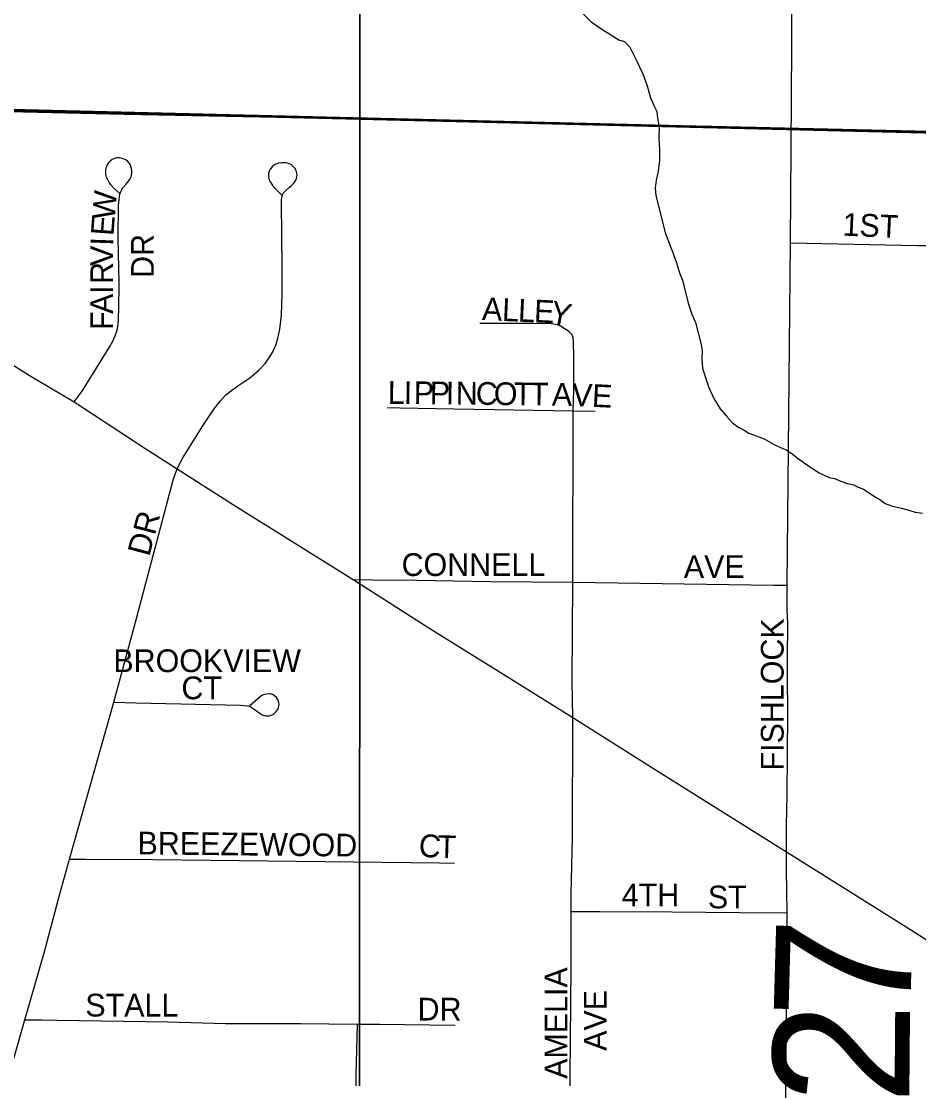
# Model space of a CAD drawing. Extents: x 0 to 68, y 0 to 52.9.
# Drawn here: x 44.8116 to 45.2063, y 37.5049 to 37.9697 of the extents above; entities that cross this region are included whole.
import ezdxf

# ---------------------------------------------------------------- set-up
doc = ezdxf.new("R2010")
doc.units = 0
for name, color, linetype in [('Default', 7, 'Continuous'), ('GM_X_Minor_River', 7, 'Continuous'), ('GM_X_State_Route', 7, 'Continuous'), ('GM_X_Township', 7, 'Continuous'), ('GM_X_Township_Road', 7, 'Continuous'), ('GM_X_Township_Road_Text', 7, 'Continuous')]:
    doc.layers.add(name, color=color, linetype=linetype)

msp = doc.modelspace()

# ---------------------------------------------------------------- linework, layer by layer
at = {"layer": 'Default'}
for points in [[(45.79985, 39.21605), (45.7821, 37.90702), (45.7586, 37.9073), (44.45233, 37.93902), (44.47349, 39.25009)], [(43.93627, 38.46518), (44.96064, 38.44451), (44.96032, 37.38586), (43.92065, 37.39833), (43.9204, 37.41034)], [(44.96064, 38.44451), (46.03674, 38.4191), (46.02513, 37.36139), (44.96032, 37.38586)], [(44.41032, 37.93957), (44.45233, 37.93902), (45.7586, 37.9073), (45.68961, 36.62483), (44.34414, 36.66665)]]:
    msp.add_lwpolyline(points, close=True, dxfattribs=at)
for points in [[(45.14983, 37.87233), (45.15013, 37.91343), (45.15051, 37.95911), (45.15046, 37.97539), (45.15077, 38.01402)], [(44.83491, 37.80242), (44.83843, 37.8072), (44.84687, 37.82055), (44.84872, 37.8237), (44.85069, 37.82675), (44.85195, 37.8291), (44.85286, 37.8311), (44.85349, 37.83299), (44.85395, 37.83471), (44.85423, 37.83671), (44.85441, 37.83808), (44.85446, 37.83992), (44.85461, 37.84297), (44.85474, 37.85476), (44.85422, 37.87439), (44.8545, 37.88879), (44.85467, 37.89131), (44.85502, 37.89368), (44.85525, 37.89449), (44.85553, 37.89509), (44.8559, 37.8957), (44.85638, 37.89646), (44.85759, 37.89789), (44.85828, 37.89874), (44.85912, 37.89986), (44.85955, 37.90051), (44.85993, 37.90131), (44.86017, 37.90211), (44.86029, 37.90307), (44.86028, 37.90413), (44.86017, 37.90493), (44.85992, 37.90586), (44.85964, 37.90653), (44.85912, 37.90734), (44.85849, 37.90802), (44.85763, 37.90877), (44.85696, 37.90915), (44.85608, 37.90945), (44.85489, 37.90968), (44.85368, 37.90963), (44.85265, 37.90938), (44.85163, 37.90893), (44.85071, 37.90824), (44.84997, 37.9075), (44.8494, 37.90664), (44.84902, 37.90561), (44.84877, 37.90447), (44.84871, 37.90382), (44.84868, 37.90306), (44.84876, 37.90231), (44.84901, 37.90125), (44.84952, 37.90014), (44.85032, 37.89875), (44.85096, 37.89789), (44.85242, 37.89631), (44.85484, 37.89419)], [(44.88016, 37.77305), (44.88269, 37.77783), (44.88633, 37.78369), (44.89116, 37.79152), (44.89606, 37.79875), (44.89907, 37.80274), (44.90168, 37.80555), (44.90418, 37.80736), (44.90695, 37.8095), (44.9121, 37.81301), (44.91611, 37.81642), (44.91898, 37.81934), (44.92102, 37.82219), (44.92247, 37.82471), (44.92357, 37.82739), (44.92445, 37.83029), (44.92537, 37.83438), (44.92604, 37.84047), (44.92636, 37.84997), (44.92635, 37.86192), (44.92604, 37.88969), (44.92612, 37.89125), (44.92625, 37.89217), (44.92645, 37.8931), (44.92667, 37.89369), (44.92702, 37.89432), (44.9274, 37.8948), (44.92816, 37.89545), (44.92966, 37.89675), (44.93053, 37.8975), (44.93153, 37.89856), (44.93234, 37.89981), (44.93272, 37.90062), (44.9329, 37.90156), (44.93294, 37.90213), (44.93287, 37.90291), (44.93271, 37.90364), (44.93246, 37.9043), (44.93204, 37.905), (44.93166, 37.90548), (44.93084, 37.90629), (44.93034, 37.90668), (44.92941, 37.9071), (44.92874, 37.9073), (44.92799, 37.90744), (44.927, 37.90751), (44.92605, 37.90746), (44.92481, 37.9073), (44.92416, 37.90709), (44.92355, 37.90685), (44.92267, 37.90635), (44.92192, 37.90568), (44.9212, 37.90481), (44.92088, 37.90426), (44.92068, 37.90373), (44.92043, 37.90273), (44.92034, 37.902), (44.92043, 37.90111), (44.92069, 37.90007), (44.92104, 37.89917), (44.92168, 37.89824), (44.92219, 37.89751), (44.92293, 37.89662), (44.92606, 37.89345)], [(45.14839, 37.72184), (45.14983, 37.87233)], [(45.14983, 37.87233), (45.20588, 37.87118), (45.22404, 37.87118), (45.23011, 37.87102)], [(45.0133, 37.83707), (45.03691, 37.83701), (45.04455, 37.83692), (45.04587, 37.83679), (45.04713, 37.83648), (45.04868, 37.83587), (45.0512, 37.83427)], [(45.05433, 37.79849), (45.05458, 37.80758), (45.05456, 37.82441), (45.05452, 37.8267), (45.05448, 37.82884), (45.05425, 37.83068), (45.05401, 37.83143), (45.0537, 37.83207), (45.05259, 37.83328), (45.0512, 37.83427)], [(44.97273, 37.79998), (44.97805, 37.7998), (45.00221, 37.79936), (45.05433, 37.79849)], [(45.05412, 37.72312), (45.05433, 37.79849)], [(45.05433, 37.79849), (45.06403, 37.79835)], [(44.85236, 37.67039), (44.86189, 37.70565), (44.87027, 37.7371), (44.87854, 37.76854), (44.88016, 37.77305)], [(44.95765, 37.72432), (44.96631, 37.72424), (44.98563, 37.72405), (45.01796, 37.72346), (45.05412, 37.72312)], [(45.05414, 37.66367), (45.05388, 37.6798), (45.05412, 37.72312)], [(45.05412, 37.72312), (45.14238, 37.72193), (45.14839, 37.72184)], [(45.14861, 37.69017), (45.14866, 37.70476), (45.14847, 37.71129), (45.14839, 37.72184)], [(45.14814, 37.60465), (45.14814, 37.61635), (45.14836, 37.62942), (45.14867, 37.66545), (45.14858, 37.68185), (45.14861, 37.69017)], [(44.83295, 37.60148), (44.85236, 37.67039)], [(44.85236, 37.67039), (44.86198, 37.67016), (44.90803, 37.66909), (44.90971, 37.66899), (44.91133, 37.66878), (44.91237, 37.66848), (44.91308, 37.66812), (44.91381, 37.66756), (44.91453, 37.66704), (44.91563, 37.66626), (44.91675, 37.66543), (44.91761, 37.66494), (44.9184, 37.66461), (44.91921, 37.66443), (44.91993, 37.6644), (44.92077, 37.66452), (44.92156, 37.6647), (44.92238, 37.66509), (44.92299, 37.66555), (44.92345, 37.66602), (44.92387, 37.6665), (44.92435, 37.6671), (44.92462, 37.66757), (44.92484, 37.66819), (44.92495, 37.66867), (44.92501, 37.66957), (44.92495, 37.67023), (44.92478, 37.67089), (44.92447, 37.67167), (44.92425, 37.672), (44.92383, 37.67257), (44.92323, 37.67314), (44.92286, 37.67343), (44.92218, 37.67379), (44.9217, 37.67392), (44.92116, 37.67401), (44.92038, 37.67408), (44.91954, 37.67402), (44.91876, 37.67389), (44.91818, 37.67368), (44.9174, 37.67332), (44.9168, 37.6729), (44.91564, 37.67192), (44.91215, 37.6688)], [(45.05339, 37.57852), (45.05339, 37.58617), (45.05409, 37.61108), (45.05414, 37.66367)], [(44.81318, 37.53091), (44.82172, 37.5603), (44.82855, 37.58565), (44.83295, 37.60148)], [(44.83295, 37.60148), (44.84017, 37.60145), (44.86951, 37.60131), (44.99561, 37.59982), (45.00217, 37.59965)], [(45.14842, 37.57791), (45.14818, 37.59673), (45.14814, 37.60465)], [(45.0529, 37.48225), (45.0529, 37.49022), (45.05337, 37.55402), (45.05339, 37.57852)], [(45.05339, 37.57852), (45.06607, 37.57844), (45.09763, 37.57824), (45.12744, 37.57805), (45.14842, 37.57791)], [(45.14747, 37.48118), (45.1476, 37.48856), (45.14788, 37.4984), (45.14842, 37.57791)], [(44.7737, 37.38631), (44.77418, 37.38918), (44.77571, 37.39488), (44.79524, 37.46651), (44.8022, 37.49277), (44.81318, 37.53091)], [(44.81318, 37.53091), (44.82075, 37.53078), (44.82728, 37.53067), (44.87616, 37.53001), (44.90152, 37.52919), (44.93446, 37.52919), (44.95931, 37.529)], [(44.95931, 37.529), (44.9587, 37.50654), (44.95878, 37.49245), (44.95877, 37.49083), (44.95889, 37.48984), (44.95914, 37.48902), (44.95947, 37.48814), (44.95997, 37.48724), (44.96055, 37.4865), (44.96105, 37.48587), (44.96154, 37.48534), (44.96191, 37.48496), (44.96254, 37.48451), (44.96332, 37.48418), (44.96438, 37.48394), (44.96519, 37.48381), (44.96679, 37.48366), (44.96851, 37.48356), (44.98874, 37.48327), (45.01464, 37.48288), (45.03824, 37.48261), (45.0529, 37.48225)], [(44.95931, 37.529), (44.96943, 37.52892), (45.00246, 37.52849)]]:
    msp.add_lwpolyline(points, dxfattribs=at)
at = {"layer": 'GM_X_Minor_River'}
for points in [[(45.05863, 37.97315), (45.06216, 37.96947), (45.06652, 37.96657), (45.07088, 37.96367), (45.07445, 37.9616), (45.07684, 37.96075), (45.0792, 37.95829), (45.0819, 37.95302), (45.08498, 37.94654), (45.08688, 37.94129), (45.08838, 37.93604), (45.08991, 37.9324), (45.09106, 37.92997), (45.09141, 37.92715), (45.09213, 37.92312), (45.09203, 37.91831), (45.09233, 37.91349), (45.09223, 37.90868), (45.09174, 37.90387), (45.09085, 37.89988), (45.09038, 37.89628)], [(45.09038, 37.89628), (45.09071, 37.89306), (45.09183, 37.88863), (45.09331, 37.88258), (45.0948, 37.87693), (45.0967, 37.87168), (45.09785, 37.86884), (45.09861, 37.86682), (45.09975, 37.86359), (45.10126, 37.85875), (45.1024, 37.85592), (45.10351, 37.85108), (45.105, 37.84543), (45.10652, 37.84099), (45.10805, 37.83735), (45.11066, 37.82766), (45.111, 37.82485), (45.11094, 37.82164), (45.11125, 37.81722), (45.11238, 37.81359), (45.11389, 37.80874), (45.1162, 37.80388), (45.11891, 37.79941), (45.12166, 37.79615), (45.12441, 37.79328), (45.12718, 37.79122), (45.12956, 37.78997), (45.13154, 37.78873), (45.13353, 37.78788), (45.13831, 37.78618), (45.14069, 37.78493), (45.14268, 37.78369), (45.14546, 37.78243), (45.14824, 37.78117), (45.15062, 37.77952), (45.15339, 37.77745), (45.15734, 37.77456), (45.16249, 37.77125), (45.16686, 37.76916), (45.16926, 37.76871), (45.17125, 37.76787), (45.17484, 37.76659), (45.17724, 37.76614), (45.17962, 37.76489), (45.18201, 37.76404), (45.18399, 37.76279), (45.18636, 37.76114), (45.18914, 37.75948), (45.19152, 37.75783), (45.1947, 37.75656), (45.1987, 37.75568), (45.20189, 37.75481), (45.20468, 37.75395), (45.20788, 37.75348)]]:
    msp.add_lwpolyline(points, dxfattribs=at)
at = {"layer": 'GM_X_State_Route'}
msp.add_lwpolyline([(44.54231, 37.98537), (44.58338, 37.95928), (44.62473, 37.93299), (44.63484, 37.92679), (44.64377, 37.92108), (44.69622, 37.88784), (44.71909, 37.87397), (44.77962, 37.83631), (44.81636, 37.81343), (44.83491, 37.80242), (44.86599, 37.78206), (44.88016, 37.77305), (44.9046, 37.75749), (44.95765, 37.72432), (44.9925, 37.70213), (45.02038, 37.68482), (45.05414, 37.66367), (45.06975, 37.6539), (45.09194, 37.63991), (45.14814, 37.60465), (45.20303, 37.57021), (45.21358, 37.56348)], dxfattribs=at)
at = {"layer": 'GM_X_Township'}
for points in [[(50.34506, 37.77433), (49.87003, 37.78728), (49.7424, 37.78907), (49.09193, 37.81286), (48.42924, 37.83782), (47.97584, 37.8521), (47.09341, 37.87493), (46.43542, 37.88698), (45.78152, 37.90751), (45.76356, 37.9078), (44.77759, 37.93161), (44.12143, 37.94309), (43.3203, 37.94792), (43.31455, 37.9477), (43.13228, 37.95106), (43.13722, 38.12535), (43.1394, 38.18651), (43.13947, 38.19396), (43.15039, 38.61621), (43.15805, 38.89613)], [(43.06441, 32.7683), (43.08393, 33.99592), (43.08445, 34.02868), (43.09249, 34.65268), (43.09292, 34.68642), (43.10458, 35.31419), (43.1053, 35.34562), (43.1113, 36.01383), (43.1191, 36.64269), (43.12347, 37.01757), (43.12518, 37.25841), (43.12908, 37.42523), (43.12464, 37.49311), (43.12504, 37.51468), (43.13199, 37.8314), (43.13205, 37.85841), (43.13228, 37.95106), (43.31455, 37.9477), (43.3203, 37.94792), (44.12143, 37.94309), (44.77759, 37.93161), (45.76356, 37.9078)]]:
    msp.add_lwpolyline(points, dxfattribs=at)
at = {"layer": 'GM_X_Township_Road'}
msp.add_lwpolyline([(44.7872, 37.93047), (44.85691, 37.92882), (44.93892, 37.9272), (45.11526, 37.9236), (45.28748, 37.91961), (45.33668, 37.91828), (45.4638, 37.91529), (45.57041, 37.9127), (45.66883, 37.91037), (45.75084, 37.90855), (45.76151, 37.90822)], dxfattribs=at)

# ---------------------------------------------------------------- texts
at = {"layer": 'Default'}
for s, rotation, p in [('W', 85.0674, (44.85272, 37.88217)), ('E', 85.8988, (44.85222, 37.87519)), ('1ST', 357.5117, (45.17258, 37.8755)), ('DR', 90, (44.86995, 37.8569)), ('V', 89.9703, (44.85207, 37.86218)), ('I', 88.0326, (44.85207, 37.87089)), ('R', 89.9514, (44.85206, 37.85426)), ('I', 89.985, (44.85206, 37.84986)), ('A', 89.9563, (44.85206, 37.84106)), ('A', 357.4203, (45.01409, 37.83842)), ('L', 357.4309, (45.02288, 37.83802)), ('L', 357.4309, (45.02991, 37.83771)), ('E', 357.4036, (45.03695, 37.83739)), ('Y', 348.5572, (45.04357, 37.83712)), ('F', 89.9727, (44.85205, 37.83402)), ('L', 359.3716, (44.97276, 37.80158)), ('I', 359.3609, (44.97979, 37.80151)), ('P', 359.3716, (44.98419, 37.80146)), ('P', 359.3679, (44.99123, 37.80138)), ('I', 359.3882, (44.99827, 37.8013)), ('N', 359.3661, (45.00267, 37.80126)), ('C', 359.3648, (45.01147, 37.80116)), ('O', 359.3735, (45.01939, 37.80107)), ('T', 359.3716, (45.02819, 37.80098)), ('T', 359.3543, (45.03522, 37.8009)), ('A', 359.1257, (45.04489, 37.80079)), ('V', 357.5513, (45.05362, 37.80066)), ('E', 357.0202, (45.06238, 37.80029)), ('DR', 75.2542, (44.86794, 37.73413)), ('CONNELL', 0, (44.97889, 37.7259)), ('AVE', 0, (45.10297, 37.72502)), ('FISHLOCK', 90, (45.14685, 37.64042)), ('BROOKVIEW', 0, (44.85217, 37.68366)), ('CT', 0, (44.88209, 37.67174)), ('BREEZEWOOD', 359.4035, (44.86275, 37.60358)), ('C', 355.3815, (44.98613, 37.60269)), ('T', 358.3617, (44.9946, 37.60202)), ('4TH', 0, (45.07569, 37.5807)), ('ST', 0, (45.11353, 37.57982)), ('AMELIA', 90, (45.05181, 37.5049)), ('STALL', 0, (44.83985, 37.5323)), ('DR', 0, (44.98593, 37.53054)), ('AVE', 90, (45.06902, 37.51722))]:
    msp.add_text(s, height=0.01, rotation=rotation, dxfattribs=at).set_placement(p)
at = {"layer": 'GM_X_Township_Road_Text'}
for s, rotation, p in [('7', 88.3916, (45.20238, 37.53)), ('2', 89.5103, (45.20207, 37.49364))]:
    msp.add_text(s, height=0.06, rotation=rotation, dxfattribs=at).set_placement(p)

doc.saveas('drawing.dxf')
